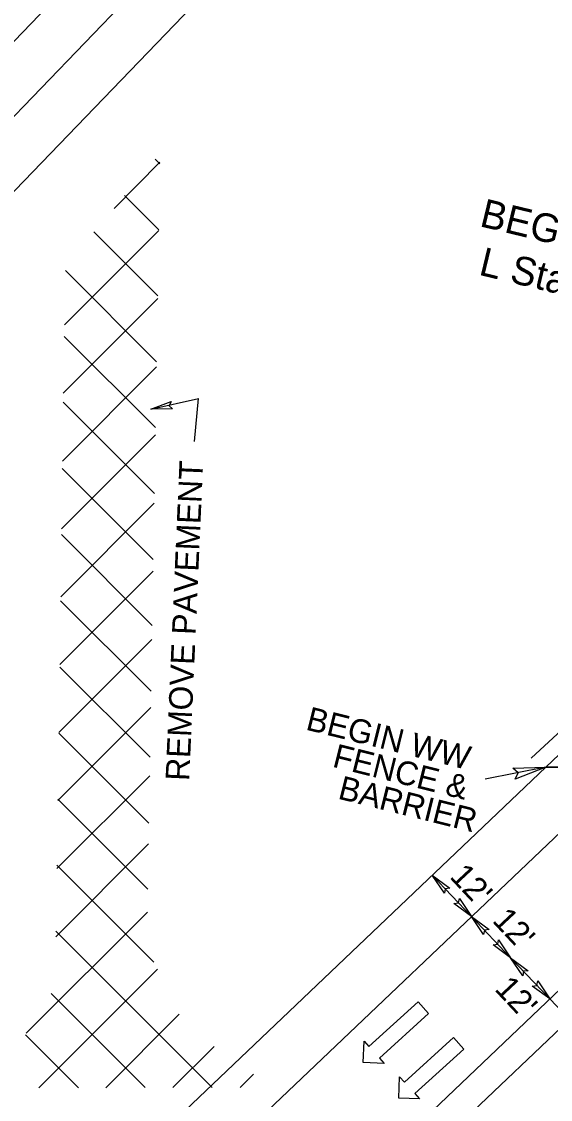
# Model space of a CAD drawing. Extents: x 2389694 to 2405615, y 546931 to 573532.
# Drawn here: x 2397717.2 to 2397828.9, y 559465.7 to 559693.2 of the extents above; entities that cross this region are included whole.
import ezdxf

# ---------------------------------------------------------------- set-up
doc = ezdxf.new("R2010")
doc.units = 0
for name, color, linetype in [('Old_Level_11', 7, 'Continuous'), ('Prop Approach Slab', 7, 'Continuous'), ('Prop Approach Slab Hatching', 7, 'Continuous'), ('Prop Conc Barrier Precast Reinforced Single Face', 7, 'Continuous'), ('Prop Dimension', 7, 'Continuous'), ('Prop Dimension Text', 7, 'Continuous'), ('Prop DSN Text', 7, 'Continuous'), ('Prop EOT', 7, 'Continuous'), ('Prop Hatching', 7, 'Continuous'), ('Prop Horizontal Alignment', 7, 'Continuous'), ('Prop Lane Arrow Through CELL', 7, 'Continuous'), ('Prop Lane Lines', 7, 'Continuous')]:
    doc.layers.add(name, color=color, linetype=linetype)

# ---------------------------------------------------------------- blocks, each defined once
blk = doc.blocks.new('TERM')
at = {"layer": 'Old_Level_11'}
blk.add_lwpolyline([(-0.01375, 0.00225), (0, 0), (-0.01375, -0.0025), (-0.012, 0)], close=True, dxfattribs=at)

msp = doc.modelspace()

# ---------------------------------------------------------------- linework, layer by layer
at = {"layer": 'Prop Approach Slab'}
for p, q in [((2397827.94, 559535.82), (2397664.46, 559380.39)), ((2397725.49, 559380.46), (2397888.97, 559535.89)), ((2397827.94, 559535.82), (2397888.97, 559535.89))]:
    msp.add_line(p, q, dxfattribs=at)
at = {"layer": 'Prop Approach Slab Hatching'}
msp.add_lwpolyline([(2397907.09, 559553.11), (2397888.97, 559535.89), (2397827.94, 559535.82), (2397846.1, 559553.08)], close=True, dxfattribs=at)
at = {"layer": 'Prop Conc Barrier Precast Reinforced Single Face'}
msp.add_line((2397824.8, 559537.74), (2397872.55, 559581.72), dxfattribs=at)
at = {"layer": 'Prop Dimension'}
for p, q in [((2397744.53, 559611.38), (2397754.57, 559613.6)), ((2397753.75, 559604.57), (2397754.57, 559613.6)), ((2397827.94, 559535.82), (2397913.68, 559535.92)), ((2397812.22, 559504.31), (2397803.95, 559513.01)), ((2397820.49, 559495.61), (2397812.22, 559504.31)), ((2397828.76, 559486.92), (2397820.49, 559495.61)), ((2397832.89, 559482.57), (2397828.76, 559486.92))]:
    msp.add_line(p, q, dxfattribs=at)
for points in [[(2397749.09, 559611.42), (2397744.53, 559611.38), (2397748.83, 559612.98), (2397748.41, 559612.09)], [(2397806.49, 559509.21), (2397803.95, 559513.01), (2397807.65, 559510.28), (2397806.67, 559510.15)], [(2397809.68, 559508.11), (2397812.22, 559504.31), (2397808.52, 559507.04), (2397809.5, 559507.17)], [(2397814.76, 559500.52), (2397812.22, 559504.31), (2397815.92, 559501.58), (2397814.94, 559501.45)], [(2397817.95, 559499.41), (2397820.49, 559495.61), (2397816.79, 559498.34), (2397817.77, 559498.48)], [(2397823.03, 559491.82), (2397820.49, 559495.61), (2397824.19, 559492.89), (2397823.21, 559492.75)], [(2397826.22, 559490.71), (2397828.76, 559486.92), (2397825.06, 559489.65), (2397826.03, 559489.78)]]:
    msp.add_lwpolyline(points, close=True, dxfattribs=at)
at = {"layer": 'Prop DSN Text'}
msp.add_line((2397827.94, 559535.82), (2397815.12, 559533.31), dxfattribs=at)
at = {"layer": 'Prop EOT'}
for p, q in [((2397075.71, 558804.1), (2398839.56, 560481.03)), ((2397092.24, 558786.7), (2398856.1, 560463.63)), ((2397651.77, 559622.77), (2397777.64, 559753.44)), ((2397667.61, 559607.5), (2397793.49, 559738.19))]:
    msp.add_line(p, q, dxfattribs=at)
at = {"layer": 'Prop Hatching'}
for p, q in [((2397736.74, 559653.76), (2397746.44, 559663.47)), ((2397746.44, 559663.12), (2397745.4, 559664.15)), ((2397746.2, 559649.21), (2397738.97, 559656.44)), ((2397726.28, 559629.17), (2397746.2, 559649.08)), ((2397745.97, 559635.3), (2397732.46, 559648.81)), ((2397745.74, 559621.39), (2397726.51, 559640.62)), ((2397726.01, 559614.75), (2397745.96, 559634.7)), ((2397745.5, 559607.48), (2397726.24, 559626.75)), ((2397725.83, 559600.43), (2397745.72, 559620.32)), ((2397745.27, 559593.57), (2397725.99, 559612.86)), ((2397725.66, 559586.12), (2397745.48, 559605.94)), ((2397745.04, 559579.66), (2397725.81, 559598.88)), ((2397725.48, 559571.8), (2397745.24, 559591.55)), ((2397744.81, 559565.75), (2397725.64, 559584.91)), ((2397725.31, 559557.48), (2397745, 559577.17)), ((2397744.57, 559551.84), (2397725.47, 559570.94)), ((2397725.1, 559543.13), (2397744.76, 559562.79)), ((2397744.34, 559537.93), (2397725.3, 559556.97)), ((2397724.89, 559528.78), (2397744.52, 559548.4)), ((2397744.11, 559524.02), (2397725.1, 559543.03)), ((2397724.68, 559514.42), (2397744.28, 559534.02)), ((2397743.88, 559510.11), (2397724.89, 559529.09)), ((2397724.46, 559500.06), (2397744.04, 559519.64)), ((2397745.17, 559494.68), (2397724.69, 559515.16)), ((2397718.22, 559479.68), (2397743.79, 559505.26)), ((2397757.45, 559468.25), (2397724.48, 559501.22)), ((2397720.84, 559468.16), (2397745.89, 559493.21)), ((2397743.35, 559468.21), (2397723.47, 559488.09)), ((2397735.01, 559468.19), (2397750.53, 559483.7)), ((2397729.24, 559468.18), (2397718.04, 559479.38)), ((2397749.19, 559468.23), (2397757.86, 559476.89)), ((2397763.37, 559468.27), (2397766.16, 559471.05))]:
    msp.add_line(p, q, dxfattribs=at)
at = {"layer": 'Prop Horizontal Alignment'}
msp.add_line((2397659.69, 559615.14), (2397920.45, 559885.84), dxfattribs=at)
at = {"layer": 'Prop Lane Arrow Through CELL'}
for p, q in [((2397790.57, 559476.87), (2397800.93, 559486.29)), ((2397800.93, 559486.29), (2397803.15, 559483.85)), ((2397803.15, 559483.85), (2397792.79, 559474.43)), ((2397789.38, 559473.49), (2397789.56, 559477.98)), ((2397789.56, 559477.98), (2397790.57, 559476.87)), ((2397798.04, 559469.38), (2397808.4, 559478.8)), ((2397808.4, 559478.8), (2397810.62, 559476.36)), ((2397810.62, 559476.36), (2397800.26, 559466.94)), ((2397793.8, 559473.32), (2397789.38, 559473.49)), ((2397792.79, 559474.43), (2397793.8, 559473.32)), ((2397796.85, 559466), (2397797.03, 559470.49)), ((2397797.03, 559470.49), (2397798.04, 559469.38)), ((2397801.27, 559465.83), (2397796.85, 559466)), ((2397800.26, 559466.94), (2397801.27, 559465.83))]:
    msp.add_line(p, q, dxfattribs=at)
at = {"layer": 'Prop Lane Lines'}
msp.add_line((2397075.71, 558804.1), (2398839.56, 560481.03), dxfattribs=at)

# ---------------------------------------------------------------- block references
at = {"layer": 'Prop DSN Text', "xscale": 500.0000000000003, "yscale": 499.99999999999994, "rotation": 11.085944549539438}
msp.add_blockref('TERM', (2397827.94, 559535.82), dxfattribs=at)

# ---------------------------------------------------------------- texts
at = {"layer": 'Prop Dimension Text'}
for s, height, rotation, p in [('BEGIN NOISE WALL', 6, 346.4323, (2397813.72, 559650.03)), (' L Sta. 114+15.00', 6, 346.4323, (2397811.38, 559640.31)), ('REMOVE PAVEMENT', 5, 87.4863, (2397752.61, 559532.87)), ("12'", 5, 313.1053, (2397807.42, 559512.61)), ("12'", 5, 313.1053, (2397816.42, 559503.33)), ("12'", 5, 313.1053, (2397816.91, 559488.89))]:
    msp.add_text(s, height=height, rotation=rotation, dxfattribs=at).set_placement(p)
at = {"layer": 'Prop DSN Text'}
for s, p in [('BEGIN WW ', (2397777.02, 559543.8)), ('FENCE &', (2397782.65, 559535.96)), ('BARRIER', (2397783.81, 559529.23))]:
    msp.add_text(s, height=5, rotation=346, dxfattribs=at).set_placement(p)

doc.saveas('drawing.dxf')
